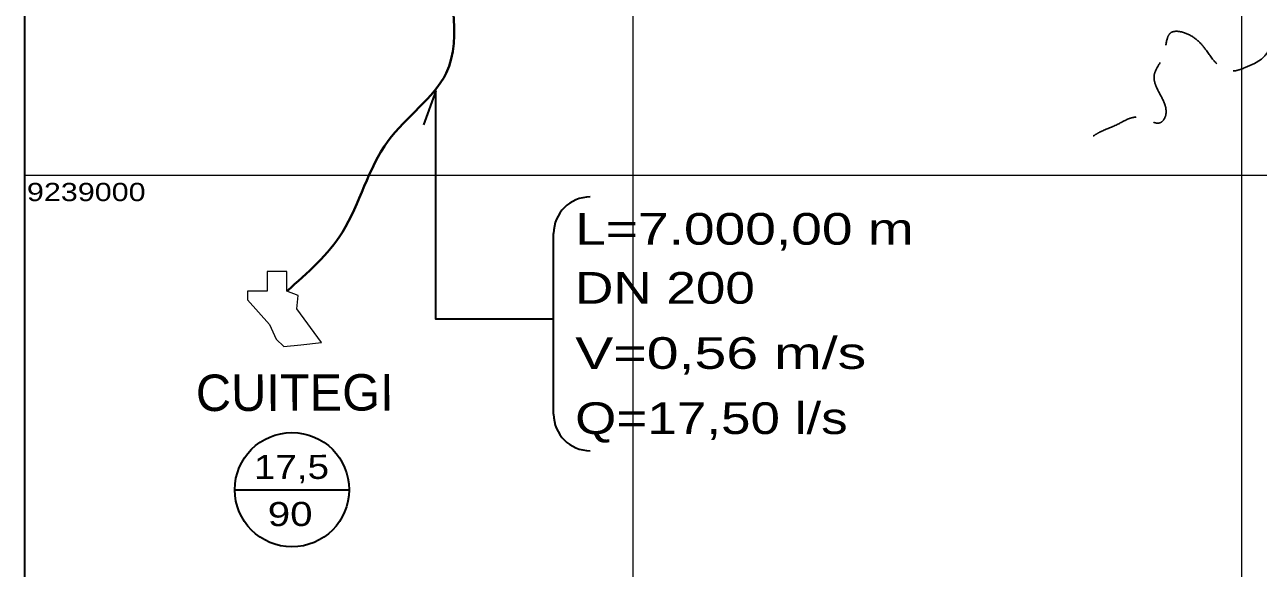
# Model space of a CAD drawing. Extents: x -4 to 42046, y -3 to 29697.
# Drawn here: x 23908 to 27137, y 12173 to 13596 of the extents above; entities that cross this region are included whole.
import ezdxf
from ezdxf.enums import TextEntityAlignment as Align

# ---------------------------------------------------------------- set-up
doc = ezdxf.new("R2010")
doc.units = 0
doc.header["$LTSCALE"] = 32
doc.linetypes.add('DOT_DASHED', pattern=[7.7, 5, -1.2, 0.3, -1.2])
doc.linetypes.add('LONG_DASHED', pattern=[7.5, 6, -1.5])
for name, color, linetype, lineweight in [('1', 7, 'DOT_DASHED', 13), ('5', 7, 'LONG_DASHED', 25), ('6', 7, 'Continuous', 40), ('63', 7, 'Continuous', 25), ('8', 7, 'Continuous', 35), ('9', 7, 'Continuous', 40)]:
    doc.layers.add(name, color=color, linetype=linetype, lineweight=lineweight)

msp = doc.modelspace()

# ---------------------------------------------------------------- linework, layer by layer
at = {"layer": '1', "linetype": 'Continuous'}
msp.add_lwpolyline([(24594.16, 12898.49), (24594.16, 12949.95), (24542.64, 12949.95), (24542.64, 12898.49), (24491.12, 12898.49), (24491.12, 12876.27), (24549.04, 12810.88), (24565.65, 12773.11), (24585.96, 12753.77), (24630.26, 12758.38), (24684.55, 12764.02), (24620.11, 12852.32), (24623.8, 12887.32)], close=True, dxfattribs=at)
at = {"layer": '5'}
msp.add_spline([(27654.38, 13409.42), (27579.6, 13443.73), (27529.72, 13474.09), (27454.19, 13489.13), (27394.85, 13464.06), (27340.28, 13452.65), (27285.56, 13488.62), (27231.63, 13532.63), (27190.61, 13554.19), (27152.2, 13513.13), (27106.91, 13486.18), (27065.69, 13475.06), (27029.89, 13492.14), (26998.84, 13531.24), (26943.02, 13575.07), (26907.27, 13574.97), (26894.31, 13541.24), (26878.63, 13495.82), (26864.29, 13464.84), (26876.8, 13418.81), (26893.41, 13382.42), (26893.48, 13356.3), (26878.41, 13339.06), (26867.52, 13339.03), (26842.62, 13351.33), (26801.37, 13351.21), (26767.05, 13334.61), (26721.05, 13314.53), (26704.57, 13304.86)], degree=3, dxfattribs=at)
at = {"layer": '6'}
msp.add_spline([(25532.33, 14368.35), (25240.25, 14300.64), (25075.5, 14084.68), (25010.89, 13813.92), (25010.89, 13469.02), (24859.06, 13291.73), (24739.53, 13053.21), (24594.16, 12898.49)], degree=3, dxfattribs=at)
at = {"layer": '63', "lineweight": 13}
for p, q in [((25500.63, 10019.66), (25500.63, 18929.66)), ((27093.44, 10019.66), (27093.44, 18929.66)), ((41110.1, 13201.8), (23907.83, 13201.8))]:
    msp.add_line(p, q, dxfattribs=at)
at = {"layer": '63', "lineweight": 35}
msp.add_lwpolyline([(41110.1, 10019.66), (23907.83, 10019.66), (23907.83, 18929.66)], dxfattribs=at)
at = {"layer": '8'}
msp.add_line((25292.3, 12576.31), (25292.3, 13049.7), dxfattribs=at)
msp.add_lwpolyline([(25292.3, 12824.97), (24983.57, 12824.97), (24983.57, 13423.35), (24951.9, 13334.29)], dxfattribs=at)
for centre, start_param, end_param in [((25387.87, 13049.7), 4.712389, 6.2831853), ((25387.87, 13049.7), 4.712389, 6.2831853), ((25387.87, 13049.7), 4.712389, 6.2831853), ((25387.87, 12576.31), 6.2831853, 7.8539816)]:
    msp.add_ellipse(centre, major_axis=(-95.57, 0), ratio=0.998913, start_param=start_param, end_param=end_param, dxfattribs=at)
at = {"layer": '9', "lineweight": 35}
msp.add_line((24457.8, 12378.73), (24757.06, 12378.73), dxfattribs=at)
msp.add_circle((24607.43, 12378.73), 149.63, dxfattribs=at)

# ---------------------------------------------------------------- texts
at = {"layer": '8'}
for s, height, width, p in [('9239000', 47.73, 1.25, (23913.73, 13134.31)), ('L=7.000,00 m', 82.98, 1.3, (25348.6, 13020.17)), ('DN 200', 82.98, 1.25, (25348.6, 12865.67)), ('V=0,56 m/s', 82.98, 1.35, (25348.6, 12695.08)), ('Q=17,50 l/s', 82.98, 1.25, (25348.6, 12524.49))]:
    msp.add_text(s, height=height, dxfattribs=dict(at, width=width)).set_placement(p)
at = {"layer": '9'}
msp.add_text('CUITEGI', height=95.46, rotation=0.17, dxfattribs=at).set_placement((24356.01, 12584.6))
for s, width, p in [('17,5', 1.2, (24606.16, 12406.79)), ('90', 1.25, (24602.8, 12283.57))]:
    msp.add_text(s, height=63, rotation=0.17, dxfattribs=dict(at, width=width)).set_placement(p, align=Align.CENTER)

doc.saveas('drawing.dxf')
